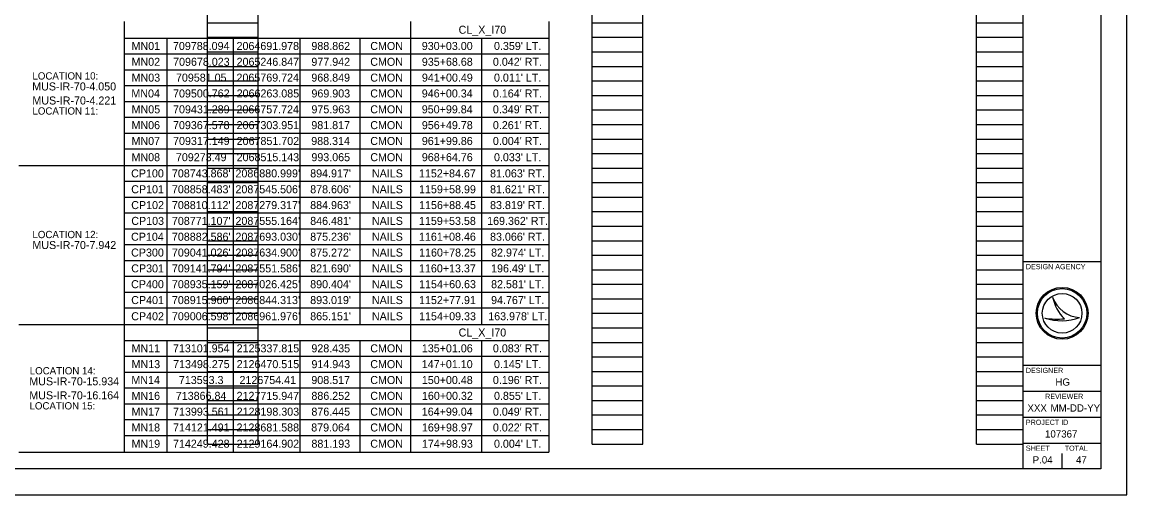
# Model space of a CAD drawing. Extents: x 0 to 34, y 0 to 22.
# Drawn here: x 12.68 to 34, y 0 to 9.11 of the extents above; entities that cross this region are included whole.
import ezdxf

# ---------------------------------------------------------------- set-up
doc = ezdxf.new("R2010")
doc.units = 0
for name, color, linetype in [('Default', 7, 'Continuous'), ('SH_Border', 7, 'Continuous'), ('SH_Cut_Line', 7, 'Continuous'), ('SH_Data', 7, 'Continuous'), ('SH_Text', 7, 'Continuous')]:
    doc.layers.add(name, color=color, linetype=linetype)

msp = doc.modelspace()

# ---------------------------------------------------------------- linework, layer by layer
at = {"layer": 'Default'}
for p, q in [((14.653, 9.126), (14.653, 0.826)), ((20.177, 9.126), (20.177, 0.826)), ((22.846, 9.126), (22.846, 0.826)), ((14.653, 8.806), (22.846, 8.806)), ((15.477, 8.806), (15.477, 3.283)), ((16.759, 8.806), (16.759, 3.283)), ((18.041, 8.806), (18.041, 3.283)), ((19.2, 8.806), (19.2, 3.283)), ((21.55, 8.806), (21.55, 3.283)), ((14.653, 8.501), (22.846, 8.501)), ((14.653, 8.195), (22.846, 8.195)), ((14.653, 7.89), (22.846, 7.89)), ((14.653, 7.585), (22.846, 7.585)), ((14.653, 7.28), (22.846, 7.28)), ((14.653, 6.975), (22.846, 6.975)), ((14.653, 6.67), (22.846, 6.67)), ((12.624, 6.349), (22.846, 6.349)), ((14.653, 6.044), (22.846, 6.044)), ((14.653, 5.739), (22.846, 5.739)), ((14.653, 5.434), (22.846, 5.434)), ((14.653, 5.129), (22.846, 5.129)), ((14.653, 4.824), (22.846, 4.824)), ((14.653, 4.519), (22.846, 4.519)), ((14.653, 4.213), (22.846, 4.213)), ((14.653, 3.908), (22.846, 3.908)), ((14.653, 3.603), (22.846, 3.603)), ((12.624, 3.283), (22.846, 3.283)), ((14.653, 2.978), (22.846, 2.978)), ((15.477, 2.978), (15.477, 0.826)), ((16.759, 2.978), (16.759, 0.826)), ((18.041, 2.978), (18.041, 0.826)), ((19.2, 2.978), (19.2, 0.826)), ((21.55, 2.978), (21.55, 0.826)), ((14.653, 2.672), (22.846, 2.672)), ((14.653, 2.367), (22.846, 2.367)), ((14.653, 2.062), (22.846, 2.062)), ((14.653, 1.757), (22.846, 1.757)), ((14.653, 1.452), (22.846, 1.452)), ((14.653, 1.147), (22.846, 1.147)), ((12.624, 0.826), (22.846, 0.826))]:
    msp.add_line(p, q, dxfattribs=at)
at = {"layer": 'SH_Border'}
for p, q in [((32, 0.5), (32, 21.5)), ((32, 4.5), (33.5, 4.5)), ((32, 2.5), (33.5, 2.5)), ((32, 2), (33.5, 2)), ((32, 1.5), (33.5, 1.5)), ((32, 1), (33.5, 1))]:
    msp.add_line(p, q, dxfattribs=at)
msp.add_lwpolyline([(1.5, 21.5), (33.5, 21.5), (33.5, 0.5), (1.5, 0.5)], close=True, dxfattribs=at)
at = {"layer": 'SH_Cut_Line'}
msp.add_lwpolyline([(0, 0), (34, 0), (34, 22), (0, 22)], close=True, dxfattribs=at)
at = {"layer": 'SH_Data'}
for p, q in [((16.26, 0.98), (16.26, 21.14)), ((17.24, 0.98), (17.24, 21.14)), ((23.68, 0.98), (23.68, 21.14)), ((24.66, 0.98), (24.66, 21.14)), ((31.1, 0.98), (31.1, 21.14)), ((32, 0.98), (32, 21.14)), ((16.26, 9.1), (17.24, 9.1)), ((23.68, 9.1), (24.66, 9.1)), ((31.1, 9.1), (32, 9.1)), ((16.26, 8.82), (17.24, 8.82)), ((23.68, 8.82), (24.66, 8.82)), ((31.1, 8.82), (32, 8.82)), ((16.26, 8.54), (17.24, 8.54)), ((23.68, 8.54), (24.66, 8.54)), ((31.1, 8.54), (32, 8.54)), ((16.26, 8.26), (17.24, 8.26)), ((23.68, 8.26), (24.66, 8.26)), ((31.1, 8.26), (32, 8.26)), ((16.26, 7.98), (17.24, 7.98)), ((23.68, 7.98), (24.66, 7.98)), ((31.1, 7.98), (32, 7.98)), ((16.26, 7.7), (17.24, 7.7)), ((23.68, 7.7), (24.66, 7.7)), ((31.1, 7.7), (32, 7.7)), ((16.26, 7.42), (17.24, 7.42)), ((23.68, 7.42), (24.66, 7.42)), ((31.1, 7.42), (32, 7.42)), ((16.26, 7.14), (17.24, 7.14)), ((23.68, 7.14), (24.66, 7.14)), ((31.1, 7.14), (32, 7.14)), ((16.26, 6.86), (17.24, 6.86)), ((23.68, 6.86), (24.66, 6.86)), ((31.1, 6.86), (32, 6.86)), ((16.26, 6.58), (17.24, 6.58)), ((23.68, 6.58), (24.66, 6.58)), ((31.1, 6.58), (32, 6.58)), ((16.26, 6.3), (17.24, 6.3)), ((23.68, 6.3), (24.66, 6.3)), ((31.1, 6.3), (32, 6.3)), ((16.26, 6.02), (17.24, 6.02)), ((23.68, 6.02), (24.66, 6.02)), ((31.1, 6.02), (32, 6.02)), ((16.26, 5.74), (17.24, 5.74)), ((23.68, 5.74), (24.66, 5.74)), ((31.1, 5.74), (32, 5.74)), ((16.26, 5.46), (17.24, 5.46)), ((23.68, 5.46), (24.66, 5.46)), ((31.1, 5.46), (32, 5.46)), ((16.26, 5.18), (17.24, 5.18)), ((23.68, 5.18), (24.66, 5.18)), ((31.1, 5.18), (32, 5.18)), ((16.26, 4.9), (17.24, 4.9)), ((23.68, 4.9), (24.66, 4.9)), ((31.1, 4.9), (32, 4.9)), ((16.26, 4.62), (17.24, 4.62)), ((23.68, 4.62), (24.66, 4.62)), ((31.1, 4.62), (32, 4.62)), ((16.26, 4.34), (17.24, 4.34)), ((23.68, 4.34), (24.66, 4.34)), ((31.1, 4.34), (32, 4.34)), ((16.26, 4.06), (17.24, 4.06)), ((23.68, 4.06), (24.66, 4.06)), ((31.1, 4.06), (32, 4.06)), ((16.26, 3.78), (17.24, 3.78)), ((23.68, 3.78), (24.66, 3.78)), ((31.1, 3.78), (32, 3.78)), ((32.567, 3.81), (32.567, 3.81)), ((16.26, 3.5), (17.24, 3.5)), ((23.68, 3.5), (24.66, 3.5)), ((31.1, 3.5), (32, 3.5)), ((32.75, 3.5), (32.75, 3.5)), ((33.087, 3.419), (33.087, 3.419)), ((16.26, 3.22), (17.24, 3.22)), ((23.68, 3.22), (24.66, 3.22)), ((31.1, 3.22), (32, 3.22)), ((32.417, 3.41), (32.417, 3.41)), ((16.26, 2.94), (17.24, 2.94)), ((23.68, 2.94), (24.66, 2.94)), ((31.1, 2.94), (32, 2.94)), ((16.26, 2.66), (17.24, 2.66)), ((23.68, 2.66), (24.66, 2.66)), ((31.1, 2.66), (32, 2.66)), ((16.26, 2.38), (17.24, 2.38)), ((23.68, 2.38), (24.66, 2.38)), ((31.1, 2.38), (32, 2.38)), ((16.26, 2.1), (17.24, 2.1)), ((23.68, 2.1), (24.66, 2.1)), ((31.1, 2.1), (32, 2.1)), ((16.26, 1.82), (17.24, 1.82)), ((23.68, 1.82), (24.66, 1.82)), ((31.1, 1.82), (32, 1.82)), ((16.26, 1.54), (17.24, 1.54)), ((23.68, 1.54), (24.66, 1.54)), ((31.1, 1.54), (32, 1.54)), ((16.26, 1.26), (17.24, 1.26)), ((23.68, 1.26), (24.66, 1.26)), ((31.1, 1.26), (32, 1.26)), ((16.26, 0.98), (17.24, 0.98)), ((23.68, 0.98), (24.66, 0.98)), ((31.1, 0.98), (32, 0.98)), ((32.375, 0.675), (32.375, 0.675)), ((32.75, 0.5), (32.75, 0.8))]:
    msp.add_line(p, q, dxfattribs=at)
for radius in [0.5, 0.477, 0.477, 0.382]:
    msp.add_circle((32.75, 3.5), radius, dxfattribs=at)
for centre, radius, start, end in [((33.116, 3.998), 0.58, 198.9257, 198.9319), ((33.347, 3.97), 0.796, 191.6379, 191.6421), ((33.116, 3.998), 0.58, 198.9319, 267.1657), ((33.347, 3.97), 0.796, 191.6421, 226.0947), ((32.739, 4.37), 1.013, 251.4576, 290.0832), ((32.648, 4.654), 1.266, 259.4964, 259.4995), ((32.739, 4.37), 1.013, 251.4527, 251.4576), ((32.648, 4.654), 1.266, 259.4995, 276.6672)]:
    msp.add_arc(centre, radius, start, end, dxfattribs=at)

# ---------------------------------------------------------------- texts
at = {"layer": 'Default'}
for s, p in [('CL_X_I70', (21.106, 8.889)), ('MN01', (14.796, 8.576)), ('709788.094', (15.595, 8.576)), ('2064691.978', (16.822, 8.576)), ('988.862', (18.266, 8.576)), ('CMON', (19.402, 8.576)), ('930+03.00', (20.396, 8.576)), ("0.359' LT.", (21.789, 8.576)), ('MN02', (14.796, 8.271)), ('709678.023', (15.598, 8.271)), ('2065246.847', (16.823, 8.271)), ('977.942', (18.266, 8.271)), ('CMON', (19.402, 8.271)), ('935+68.68', (20.397, 8.271)), ("0.042' RT.", (21.768, 8.271)), ('MN03', (14.797, 7.966)), ('709581.05', (15.653, 7.966)), ('2065769.724', (16.821, 7.966)), ('968.849', (18.265, 7.966)), ('CMON', (19.402, 7.966)), ('941+00.49', (20.398, 7.966)), ("0.011' LT.", (21.789, 7.966)), ('MUS-IR-70-4.050', (12.88, 7.796)), ('MUS-IR-70-4.221', (12.883, 7.525)), ('MN04', (14.793, 7.661)), ('709500.762', (15.597, 7.661)), ('2066263.085', (16.824, 7.661)), ('969.903', (18.267, 7.661)), ('CMON', (19.402, 7.661)), ('946+00.34', (20.396, 7.661)), ("0.164' RT.", (21.768, 7.661)), ('MN05', (14.797, 7.355)), ('709431.289', (15.597, 7.355)), ('2066757.724', (16.821, 7.355)), ('975.963', (18.267, 7.355)), ('CMON', (19.402, 7.355)), ('950+99.84', (20.396, 7.355)), ("0.349' RT.", (21.768, 7.355)), ('MN06', (14.795, 7.05)), ('709367.578', (15.596, 7.05)), ('2067303.951', (16.823, 7.05)), ('981.817', (18.265, 7.05)), ('CMON', (19.402, 7.05)), ('956+49.78', (20.397, 7.05)), ("0.261' RT.", (21.768, 7.05)), ('MN07', (14.795, 6.745)), ('709317.149', (15.597, 6.745)), ('2067851.702', (16.824, 6.745)), ('988.314', (18.263, 6.745)), ('CMON', (19.402, 6.745)), ('961+99.86', (20.397, 6.745)), ("0.004' RT.", (21.768, 6.745)), ('MN08', (14.795, 6.432)), ('709273.49', (15.652, 6.432)), ('2068515.143', (16.824, 6.432)), ('993.065', (18.266, 6.432)), ('CMON', (19.402, 6.432)), ('968+64.76', (20.397, 6.432)), ("0.033' LT.", (21.789, 6.432)), ('CP100', (14.788, 6.12)), ("708743.868'", (15.575, 6.12)), ("2086880.999'", (16.801, 6.12)), ("894.917'", (18.243, 6.12)), ('NAILS', (19.434, 6.12)), ('1152+84.67', (20.342, 6.12)), ("81.063' RT.", (21.713, 6.12)), ('CP101', (14.79, 5.814)), ("708858.483'", (15.575, 5.814)), ("2087545.506'", (16.801, 5.814)), ("878.606'", (18.243, 5.814)), ('NAILS', (19.434, 5.814)), ('1159+58.99', (20.343, 5.814)), ("81.621' RT.", (21.713, 5.814)), ('CP102', (14.79, 5.509)), ("708810.112'", (15.575, 5.509)), ("2087279.317'", (16.801, 5.509)), ("884.963'", (18.243, 5.509)), ('NAILS', (19.434, 5.509)), ('1156+88.45', (20.344, 5.509)), ("83.819' RT.", (21.713, 5.509)), ('CP103', (14.791, 5.204)), ("708771.107'", (15.575, 5.204)), ("2087555.164'", (16.801, 5.204)), ("846.481'", (18.243, 5.204)), ('NAILS', (19.434, 5.204)), ('1159+53.58', (20.342, 5.204)), ("169.362' RT.", (21.657, 5.204)), ('CP104', (14.787, 4.899)), ("708882.586'", (15.575, 4.899)), ("2087693.030'", (16.801, 4.899)), ("875.236'", (18.243, 4.899)), ('NAILS', (19.434, 4.899)), ('1161+08.46', (20.342, 4.899)), ("83.066' RT.", (21.713, 4.899)), ('MUS-IR-70-7.942', (12.883, 4.739)), ('CP300', (14.788, 4.594)), ("709041.026'", (15.575, 4.594)), ("2087634.900'", (16.801, 4.594)), ("875.272'", (18.243, 4.594)), ('NAILS', (19.434, 4.594)), ('1160+78.25', (20.344, 4.594)), ("82.974' LT.", (21.733, 4.594)), ('CP301', (14.79, 4.289)), ("709141.794'", (15.575, 4.289)), ("2087551.586'", (16.801, 4.289)), ("821.690'", (18.243, 4.289)), ('NAILS', (19.434, 4.289)), ('1160+13.37', (20.342, 4.289)), ("196.49' LT.", (21.733, 4.289)), ('CP400', (14.788, 3.984)), ("708935.159'", (15.575, 3.984)), ("2087026.425'", (16.801, 3.984)), ("890.404'", (18.243, 3.984)), ('NAILS', (19.434, 3.984)), ('1154+60.63', (20.344, 3.984)), ("82.581' LT.", (21.733, 3.984)), ('CP401', (14.79, 3.678)), ("708915.960'", (15.575, 3.678)), ("2086844.313'", (16.801, 3.678)), ("893.019'", (18.243, 3.678)), ('NAILS', (19.434, 3.678)), ('1152+77.91', (20.343, 3.678)), ("94.767' LT.", (21.733, 3.678)), ('CP402', (14.79, 3.366)), ("709006.598'", (15.575, 3.366)), ("2086961.976'", (16.801, 3.366)), ("865.151'", (18.243, 3.366)), ('NAILS', (19.434, 3.366)), ('1154+09.33', (20.344, 3.366)), ("163.978' LT.", (21.678, 3.366)), ('CL_X_I70', (21.106, 3.053)), ('MN11', (14.796, 2.748)), ('713101.954', (15.595, 2.748)), ('2125337.815', (16.824, 2.748)), ('928.435', (18.266, 2.748)), ('CMON', (19.402, 2.748)), ('135+01.06', (20.397, 2.748)), ("0.083' RT.", (21.768, 2.748)), ('MN13', (14.797, 2.443)), ('713498.275', (15.598, 2.443)), ('2126470.515', (16.824, 2.443)), ('914.943', (18.267, 2.443)), ('CMON', (19.402, 2.443)), ('147+01.10', (20.396, 2.443)), ("0.145' LT.", (21.789, 2.443)), ('MUS-IR-70-15.934 ', (12.824, 2.112)), ('MN14', (14.793, 2.137)), ('713593.3', (15.709, 2.137)), ('2126754.41', (16.879, 2.137)), ('908.517', (18.265, 2.137)), ('CMON', (19.402, 2.137)), ('150+00.48', (20.397, 2.137)), ("0.196' RT.", (21.768, 2.137)), ('MUS-IR-70-16.164', (12.824, 1.842)), ('MN16', (14.795, 1.832)), ('713866.84', (15.65, 1.832)), ('2127715.947', (16.823, 1.832)), ('886.252', (18.266, 1.832)), ('CMON', (19.402, 1.832)), ('160+00.32', (20.399, 1.832)), ("0.855' LT.", (21.789, 1.832)), ('MN17', (14.795, 1.527)), ('713993.561', (15.597, 1.527)), ('2128198.303', (16.824, 1.527)), ('876.445', (18.266, 1.527)), ('CMON', (19.402, 1.527)), ('164+99.04', (20.396, 1.527)), ("0.049' RT.", (21.768, 1.527)), ('MN18', (14.795, 1.222)), ('714121.491', (15.597, 1.222)), ('2128681.588', (16.822, 1.222)), ('879.064', (18.263, 1.222)), ('CMON', (19.402, 1.222)), ('169+98.97', (20.398, 1.222)), ("0.022' RT.", (21.768, 1.222)), ('MN19', (14.796, 0.909)), ('714249.428', (15.596, 0.909)), ('2129164.902', (16.824, 0.909)), ('881.193', (18.267, 0.909)), ('CMON', (19.402, 0.909)), ('174+98.93', (20.399, 0.909)), ("0.004' LT.", (21.789, 0.909))]:
    msp.add_text(s, height=0.1544, dxfattribs=at).set_placement(p)
at = {"layer": 'SH_Data'}
for s, height, p in [('DESIGN AGENCY', 0.1, (32.05, 4.35)), ('DESIGNER', 0.1, (32.05, 2.35)), ('HG', 0.14, (32.62, 2.105)), ('REVIEWER', 0.1, (32.422, 1.85)), ('XXX', 0.14, (32.081, 1.605)), ('MM-DD-YY', 0.14, (32.527, 1.605)), ('PROJECT ID', 0.1, (32.05, 1.35)), ('107367', 0.14, (32.42, 1.105)), ('SHEET', 0.1, (32.05, 0.85)), ('TOTAL', 0.1, (32.8, 0.85)), ('P.04', 0.14, (32.182, 0.605)), ('47', 0.14, (33.018, 0.605))]:
    msp.add_text(s, height=height, dxfattribs=at).set_placement(p)
at = {"layer": 'SH_Text'}
for s, p in [('LOCATION 10:', (12.884, 8.006)), ('LOCATION 11:', (12.884, 7.33)), ('LOCATION 12:', (12.884, 4.949)), ('LOCATION 14:', (12.832, 2.323)), ('LOCATION 15:', (12.827, 1.647))]:
    msp.add_text(s, height=0.14, dxfattribs=at).set_placement(p)

doc.saveas('drawing.dxf')
